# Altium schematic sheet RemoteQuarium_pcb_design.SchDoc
size 297 x 209 mm
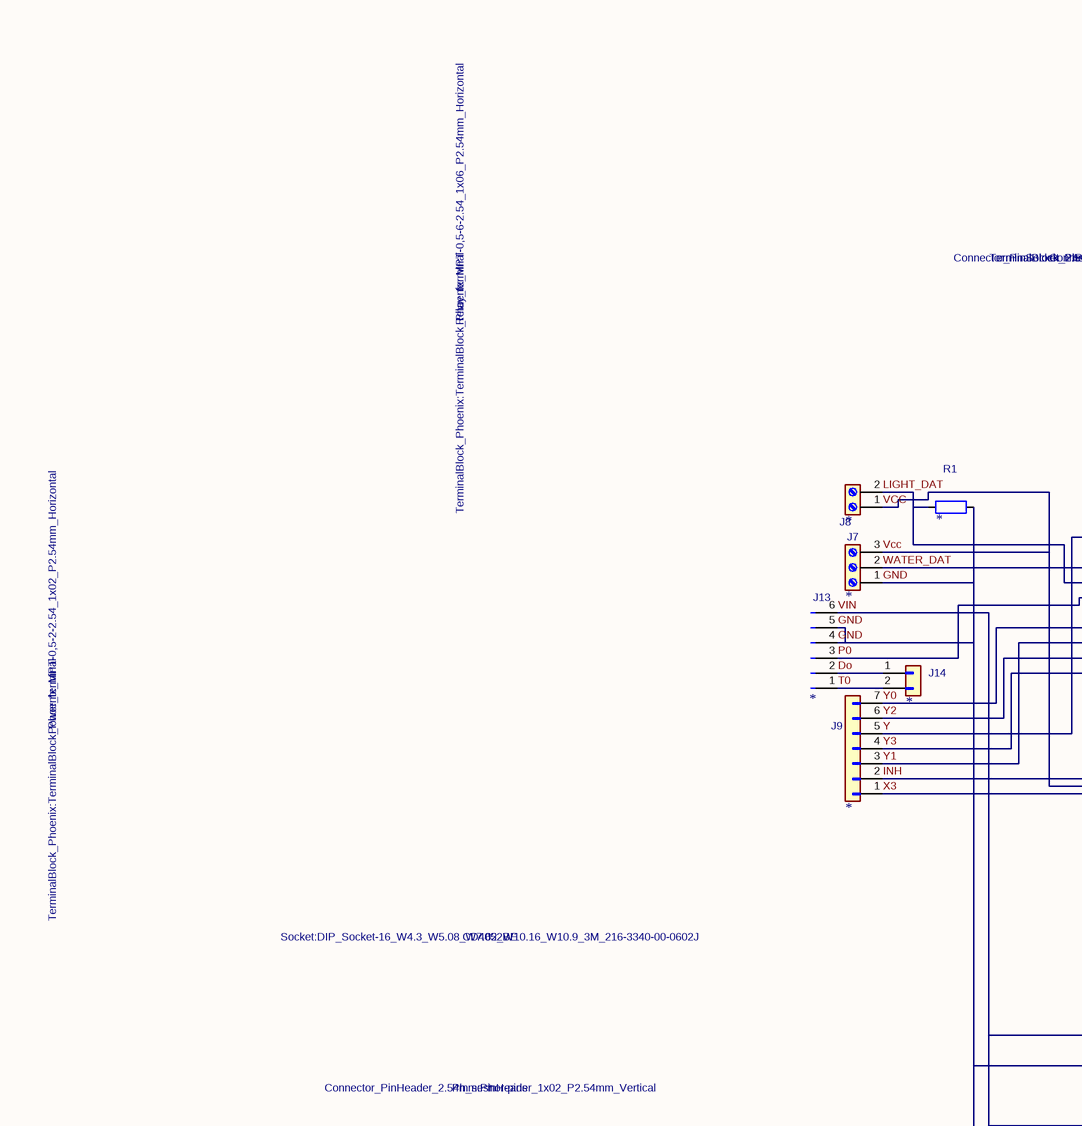
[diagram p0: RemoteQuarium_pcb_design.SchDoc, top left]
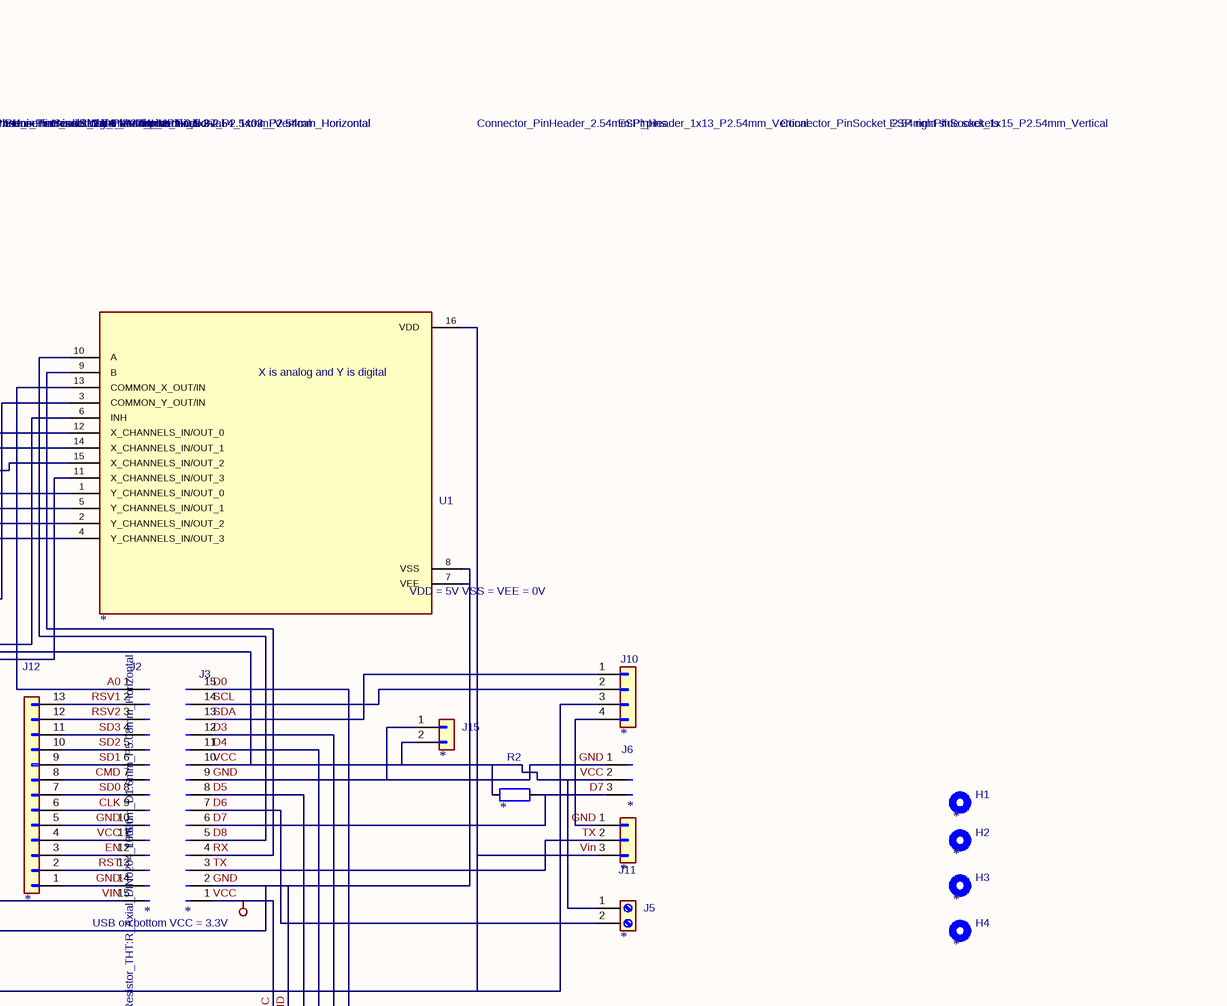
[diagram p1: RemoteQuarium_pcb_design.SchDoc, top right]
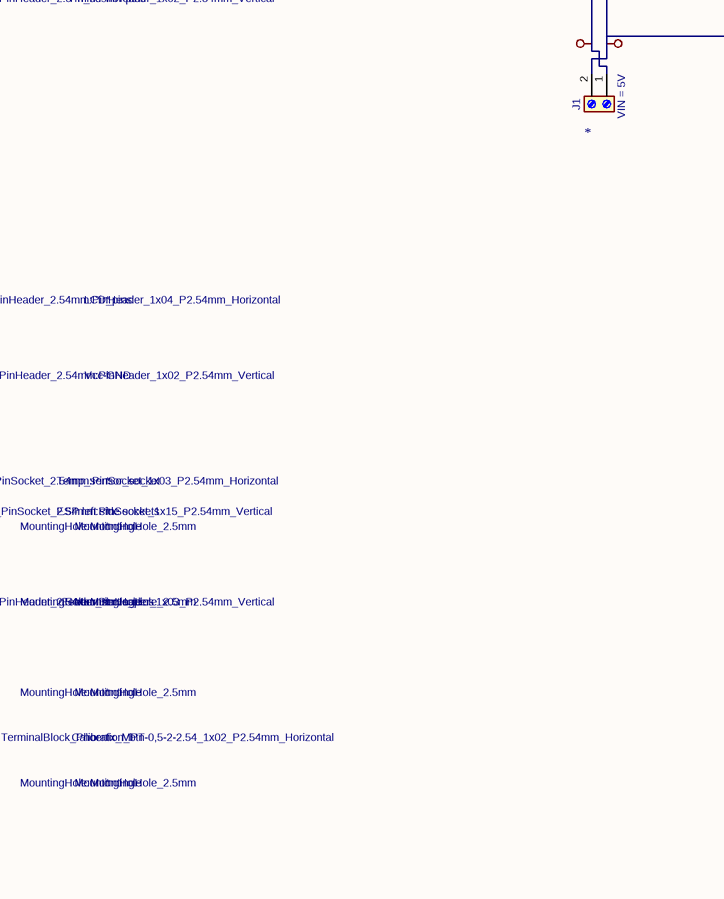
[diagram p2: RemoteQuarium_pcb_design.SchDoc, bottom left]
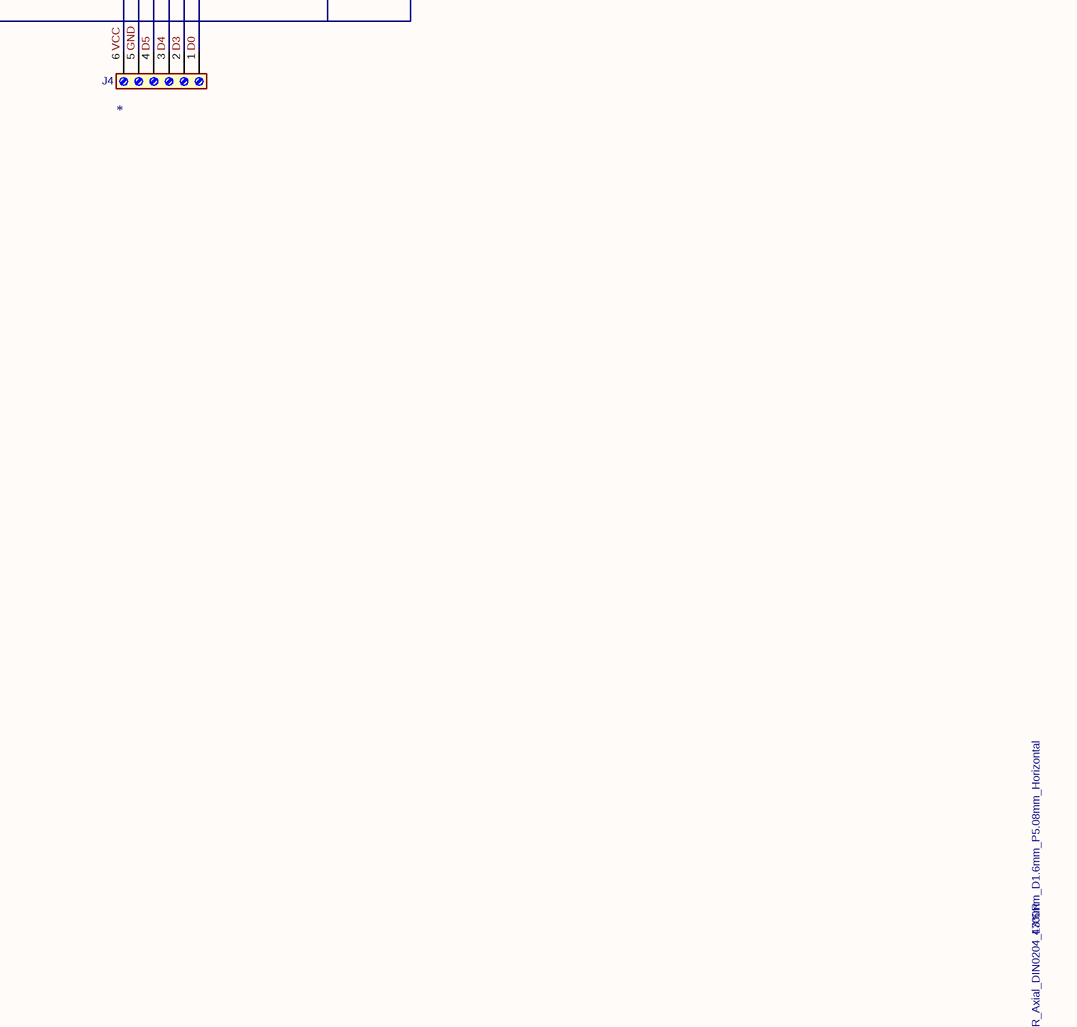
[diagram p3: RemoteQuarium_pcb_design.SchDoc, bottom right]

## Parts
(Parts that share a designator on the sheet are numbered #1, #2 ... from top to bottom, then left to right.)
*#1  *  value Light_sensor_terminal  Reference: J8  Footprint: TerminalBlock_Phoenix:TerminalBlock_Phoenix_MPT-0,5-2-2.54_1x02_P2.54mm_Horizontal
*#2  *  value 10000  Reference: R1  Footprint: Resistor_THT:R_Axial_DIN0204_L3.6mm_D1.6mm_P5.08mm_Horizontal
*#3  *  value Water_sensor_terminal  Reference: J7  Footprint: TerminalBlock_Phoenix:TerminalBlock_Phoenix_MPT-0,5-3-2.54_1x03_P2.54mm_Horizontal
*#4  *  value CD4052BE  Reference: U1  Footprint: Socket:DIP_Socket-16_W4.3_W5.08_W7.62_W10.16_W10.9_3M_216-3340-00-0602J
*#5  *  value PH_sensor_sockets  Reference: J13  Footprint: Connector_PinSocket_2.54mm:PinSocket_1x06_P2.54mm_Horizontal
*#6  *  value Ph_sesnor-pins  Reference: J14  Footprint: Connector_PinHeader_2.54mm:PinHeader_1x02_P2.54mm_Vertical
*#7  *  value MUX_pins  Reference: J9  Footprint: Connector_PinHeader_2.54mm:PinHeader_1x07_P2.54mm_Vertical
*#8  *  value LCD_pins  Reference: J10  Footprint: Connector_PinHeader_2.54mm:PinHeader_1x04_P2.54mm_Horizontal
*#9  *  value Vcc-GND  Reference: J15  Footprint: Connector_PinHeader_2.54mm:PinHeader_1x02_P2.54mm_Vertical
*#10  *  value Temp_sensor_socket  Reference: J6  Footprint: Connector_PinSocket_2.54mm:PinSocket_1x03_P2.54mm_Horizontal
*#11  *  value ESP_pins  Reference: J12  Footprint: Connector_PinHeader_2.54mm:PinHeader_1x13_P2.54mm_Vertical
*#12  *  value ESP left side sockets  Reference: J2  Footprint: Connector_PinSocket_2.54mm:PinSocket_1x15_P2.54mm_Vertical
*#13  *  value ESP right side sockets  Reference: J3  Footprint: Connector_PinSocket_2.54mm:PinSocket_1x15_P2.54mm_Vertical
*#14  *  value 4700R  Reference: R2  Footprint: Resistor_THT:R_Axial_DIN0204_L3.6mm_D1.6mm_P5.08mm_Horizontal
*#15  *  value MountingHole  Reference: H1  Footprint: MountingHole:MountingHole_2.5mm
*#16  *  value Feeder_servo_pins  Reference: J11  Footprint: Connector_PinHeader_2.54mm:PinHeader_1x03_P2.54mm_Vertical
*#17  *  value MountingHole  Reference: H2  Footprint: MountingHole:MountingHole_2.5mm
*#18  *  value MountingHole  Reference: H3  Footprint: MountingHole:MountingHole_2.5mm
*#19  *  value Calibration_btn  Reference: J5  Footprint: TerminalBlock_Phoenix:TerminalBlock_Phoenix_MPT-0,5-2-2.54_1x02_P2.54mm_Horizontal
*#20  *  value MountingHole  Reference: H4  Footprint: MountingHole:MountingHole_2.5mm
*#21  *  value Relay_terminal  Reference: J4  Footprint: TerminalBlock_Phoenix:TerminalBlock_Phoenix_MPT-0,5-6-2.54_1x06_P2.54mm_Horizontal
*#22  *  value Power_terminal  Reference: J1  Footprint: TerminalBlock_Phoenix:TerminalBlock_Phoenix_MPT-0,5-2-2.54_1x02_P2.54mm_Horizontal

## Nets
GND: *#1.1(Pin_1) *#2.2 *#3.1(Pin_1) *#3.3(Pin_3) *#4.7(VEE) *#4.8(VSS) *#4.16(VDD) *#5.4(Pin_4) *#5.5(Pin_5) *#5.6(Pin_6) *#8.3(Pin_3) *#8.4(Pin_4) *#9.1(Pin_1) *#9.2(Pin_2) *#10.1(Pin_1) *#10.2(Pin_2) *#11.1(Pin_1) *#11.4(Pin_4) *#11.5(Pin_5) *#12.10(Pin_10) *#12.11(Pin_11) *#12.14(Pin_14) *#12.15(Pin_15) *#13.1(Pin_1) *#13.2(Pin_2) *#13.9(Pin_9) *#13.10(Pin_10) *#14.1 *#16.1(Pin_1) *#16.3(Pin_3) *#19.1(Pin_1) *#21.5(Pin_5) *#21.6(Pin_6) *#22.1(Pin_1) *#22.2(Pin_2)  [also labelled VCC, VIN]
A0: *#4.13(COMMON_X_OUT/IN) *#12.1(Pin_1)
CLK: *#11.6(Pin_6) *#12.9(Pin_9)
CMD: *#11.8(Pin_8) *#12.7(Pin_7)
D0: *#13.15(Pin_15) *#21.1(Pin_1)
D3: *#13.12(Pin_12) *#21.2(Pin_2)
D4: *#13.11(Pin_11) *#21.3(Pin_3)
D5: *#13.8(Pin_8) *#21.4(Pin_4)
D6: *#13.7(Pin_7) *#19.2(Pin_2)
D7: *#10.3(Pin_3) *#13.6(Pin_6) *#14.2
D8: *#4.10(A) *#13.5(Pin_5)
Do: *#5.2(Pin_2) *#6.1(Pin_1)
EN: *#11.3(Pin_3) *#12.12(Pin_12)
INH: *#4.6(INH) *#7.2(Pin_2)
LIGHT_DAT: *#1.2(Pin_2) *#2.1 *#4.14(X_CHANNELS_IN/OUT_1)
P0: *#4.15(X_CHANNELS_IN/OUT_2) *#5.3(Pin_3)
RST: *#11.2(Pin_2) *#12.13(Pin_13)
RSV1: *#11.13(Pin_13) *#12.2(Pin_2)
RSV2: *#11.12(Pin_12) *#12.3(Pin_3)
RX: *#4.9(B) *#13.4(Pin_4)
SCL: *#8.2(Pin_2) *#13.14(Pin_14)
SD0: *#11.7(Pin_7) *#12.8(Pin_8)
SD1: *#11.9(Pin_9) *#12.6(Pin_6)
SD2: *#11.10(Pin_10) *#12.5(Pin_5)
SD3: *#11.11(Pin_11) *#12.4(Pin_4)
SDA: *#8.1(Pin_1) *#13.13(Pin_13)
T0: *#5.1(Pin_1) *#6.2(Pin_2)
TX: *#13.3(Pin_3) *#16.2(Pin_2)
WATER_DAT: *#3.2(Pin_2) *#4.12(X_CHANNELS_IN/OUT_0)
X3: *#4.11(X_CHANNELS_IN/OUT_3) *#7.1(Pin_1)
Y: *#4.3(COMMON_Y_OUT/IN) *#7.5(Pin_5)
Y0: *#4.1(Y_CHANNELS_IN/OUT_0) *#7.7(Pin_7)
Y1: *#4.5(Y_CHANNELS_IN/OUT_1) *#7.3(Pin_3)
Y2: *#4.2(Y_CHANNELS_IN/OUT_2) *#7.6(Pin_6)
Y3: *#4.4(Y_CHANNELS_IN/OUT_3) *#7.4(Pin_4)

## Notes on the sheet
- (near *#4) X is analog and Y is digital
- (near *#4) VDD = 5V
  VSS = VEE = 0V
- (near *#13) USB on bottom
  VCC = 3.3V
- (near *#22) VIN = 5V

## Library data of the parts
*#1 *#19 *#22 = Screw_Terminal_01x02
*#2 *#14 = R
*#3 = Screw_Terminal_01x03
*#4 = CD4052BE: MF: Texas Instruments; Description: \n20-V, 4:1, 2-channel general-purpose multiplexer\n
*#5 = Conn_01x06_Socket
*#6 *#9 = Conn_01x02
*#7 = Conn_01x07
*#8 = Conn_01x04
*#10 = Conn_01x03_Socket
*#11 = Conn_01x13
*#12 *#13 = Conn_01x15_Socket
*#15 *#17 *#18 *#20 = MountingHole
*#16 = Conn_01x03
*#21 = Screw_Terminal_01x06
